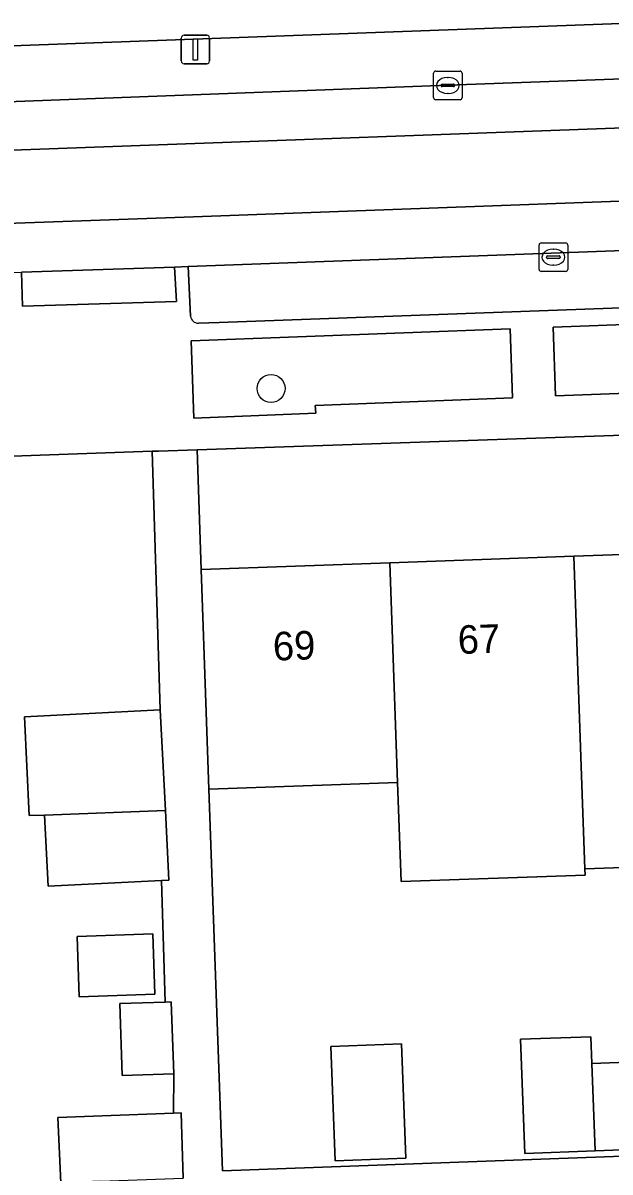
# Model space of a CAD drawing. Extents: x 160554 to 161248, y 385329 to 386506.
# Drawn here: x 160729.21 to 160749.76, y 386114.66 to 386154.93 of the extents above; entities that cross this region are included whole.
import ezdxf

# ---------------------------------------------------------------- set-up
doc = ezdxf.new("R2010")
doc.units = 0
for name, color, linetype in [('IMGEO_Boom', 7, 'Continuous'), ('IMGEO_Erf', 7, 'Continuous'), ('IMGEO_Groenvoorziening', 7, 'Continuous'), ('IMGEO_Kolk', 7, 'Continuous'), ('IMGEO_Lichtmast', 7, 'Continuous'), ('IMGEO_Pand', 7, 'Continuous'), ('IMGEO_Pand_nummerreeks', 7, 'Continuous'), ('IMGEO_Parkeervlak_open', 7, 'Continuous'), ('IMGEO_Rijbaan_lokaal_gesloten', 7, 'Continuous'), ('IMGEO_Rijbaan_lokaal_open', 7, 'Continuous'), ('IMGEO_Voetpad_open', 7, 'Continuous')]:
    doc.layers.add(name, color=color, linetype=linetype)

msp = doc.modelspace()

# ---------------------------------------------------------------- linework, layer by layer
at = {"layer": 'IMGEO_Boom'}
msp.add_circle((160737.894, 386142.121), 0.489, dxfattribs=at)
at = {"layer": 'IMGEO_Erf'}
for points in [[(160809.404, 386142.522), (160806.477, 386142.421), (160735.299, 386139.972), (160735.443, 386135.774), (160742.047, 386136.009), (160748.493, 386136.239), (160754.939, 386136.469), (160761.385, 386136.699), (160767.831, 386136.929), (160774.276, 386137.158), (160780.722, 386137.388), (160787.168, 386137.618), (160793.614, 386137.848), (160800.06, 386138.078), (160806.664, 386138.313), (160806.695, 386137.434), (160809.588, 386137.538)], [(160731.097, 386122.915), (160733.753, 386123.006), (160733.826, 386120.894), (160731.17, 386120.803)], [(160754.083, 386118.653), (160754.197, 386115.59), (160749.237, 386115.405), (160746.777, 386115.313), (160746.629, 386119.313), (160749.094, 386119.404), (160749.127, 386118.469)], [(160742.611, 386115.143), (160740.133, 386115.051), (160739.984, 386119.067), (160742.462, 386119.159)]]:
    msp.add_lwpolyline(points, close=True, dxfattribs=at)
for points in [[(160734.925, 386110.713), (160732.101, 386110.573), (160731.914, 386114.337), (160730.536, 386114.286), (160730.422, 386116.577), (160734.474, 386116.727), (160734.482, 386118.101), (160732.682, 386118.04), (160732.595, 386120.567), (160734.178, 386120.621), (160734.06, 386124.88), (160730.085, 386124.68), (160729.96, 386127.173), (160729.417, 386127.153), (160729.26, 386130.616), (160734.011, 386130.858), (160733.73, 386139.919), (160730.46, 386139.808), (160728.843, 386139.754), (160716.402, 386139.302), (160711.136, 386139.11)], [(160751.879, 386125.398), (160748.884, 386125.291), (160748.892, 386125.068), (160742.446, 386124.838), (160742.322, 386128.314), (160735.717, 386128.079), (160736.193, 386114.703), (160798.286, 386116.987)]]:
    msp.add_lwpolyline(points, dxfattribs=at)
at = {"layer": 'IMGEO_Groenvoorziening'}
msp.add_lwpolyline([(160726.584, 386154.051), (160789.885, 386156.386), (160804.496, 386156.913), (160804.459, 386158.413)], dxfattribs=at)
for points in [[(160764.098, 386144.882), (160747.766, 386144.265), (160747.847, 386141.862), (160764.177, 386142.466)], [(160746.265, 386144.21), (160735.094, 386143.792), (160735.185, 386141.081), (160739.459, 386141.254), (160739.438, 386141.527), (160746.342, 386141.798)]]:
    msp.add_lwpolyline(points, close=True, dxfattribs=at)
at = {"layer": 'IMGEO_Kolk'}
for p, q in [((160743.657, 386153.241), (160744.509, 386153.241)), ((160743.582, 386152.315), (160743.582, 386153.167)), ((160744.07, 386153.021), (160744.095, 386153.021)), ((160744.583, 386153.167), (160744.583, 386152.315)), ((160743.841, 386152.735), (160743.841, 386152.747)), ((160744.279, 386152.698), (160743.881, 386152.698)), ((160743.884, 386152.784), (160744.282, 386152.784)), ((160744.093, 386152.461), (160744.068, 386152.461)), ((160744.325, 386152.747), (160744.325, 386152.735)), ((160744.509, 386152.241), (160743.657, 386152.241)), ((160747.353, 386147.222), (160748.205, 386147.222)), ((160747.278, 386146.296), (160747.278, 386147.148)), ((160747.766, 386147.002), (160747.791, 386147.002)), ((160748.279, 386147.148), (160748.279, 386146.296)), ((160747.537, 386146.716), (160747.537, 386146.728)), ((160747.975, 386146.679), (160747.577, 386146.679)), ((160747.58, 386146.765), (160747.978, 386146.765)), ((160747.789, 386146.442), (160747.764, 386146.442)), ((160748.021, 386146.728), (160748.021, 386146.716)), ((160748.205, 386146.222), (160747.353, 386146.222))]:
    msp.add_line(p, q, dxfattribs=at)
for points in [[(160743.657, 386153.241), (160744.509, 386153.241)], [(160743.582, 386152.315), (160743.582, 386153.167)], [(160744.583, 386153.167), (160744.583, 386152.315)], [(160744.509, 386152.241), (160743.657, 386152.241)], [(160747.353, 386147.222), (160748.205, 386147.222)], [(160747.278, 386146.296), (160747.278, 386147.148)], [(160748.279, 386147.148), (160748.279, 386146.296)], [(160748.205, 386146.222), (160747.353, 386146.222)]]:
    msp.add_lwpolyline(points, dxfattribs=at)
for centre, radius, start, end in [((160743.659, 386153.165), 0.0765, 91.552, 178.448), ((160743.659, 386153.165), 0.0765, 91.552, 178.448), ((160744.507, 386153.165), 0.0765, 1.552, 88.448), ((160744.507, 386153.165), 0.0765, 1.552, 88.448), ((160743.881, 386152.744), 0.0403, 85.8775, 175.7526), ((160743.878, 386152.734), 0.0366, 178.938, 274.7102), ((160744.282, 386152.741), 0.043, 264.8664, 352.4533), ((160744.286, 386152.746), 0.0386, 1.7309, 96.639), ((160743.659, 386152.317), 0.0765, 181.552, 268.448), ((160743.659, 386152.317), 0.0765, 181.552, 268.448), ((160744.507, 386152.317), 0.0765, 271.552, 358.448), ((160744.507, 386152.317), 0.0765, 271.552, 358.448), ((160747.355, 386147.146), 0.0765, 91.552, 178.448), ((160747.355, 386147.146), 0.0765, 91.552, 178.448), ((160748.203, 386147.146), 0.0765, 1.552, 88.448), ((160748.203, 386147.146), 0.0765, 1.552, 88.448), ((160747.577, 386146.725), 0.0403, 85.8775, 175.7526), ((160747.574, 386146.715), 0.0366, 178.938, 274.7102), ((160747.978, 386146.722), 0.043, 264.8664, 352.4533), ((160747.982, 386146.727), 0.0386, 1.7309, 96.639), ((160747.355, 386146.298), 0.0765, 181.552, 268.448), ((160747.355, 386146.298), 0.0765, 181.552, 268.448), ((160748.203, 386146.298), 0.0765, 271.552, 358.448), ((160748.203, 386146.298), 0.0765, 271.552, 358.448)]:
    msp.add_arc(centre, radius, start, end, dxfattribs=at)
for centre, major_axis, ratio, start_param, end_param in [((160744.069, 386152.741), (-0.387, 0.002), 0.722429, 4.712389, 7.853982), ((160744.094, 386152.741), (-0.39, 0.002), 0.717154, 1.570796, 4.712389), ((160747.765, 386146.722), (-0.387, 0.002), 0.722429, 4.712389, 7.853982), ((160747.79, 386146.722), (-0.39, 0.002), 0.717154, 1.570796, 4.712389)]:
    msp.add_ellipse(centre, major_axis=major_axis, ratio=ratio, start_param=start_param, end_param=end_param, dxfattribs=at)
at = {"layer": 'IMGEO_Lichtmast'}
for p, q in [((160734.847, 386154.5), (160735.637, 386154.5)), ((160735.637, 386154.5), (160734.847, 386154.5)), ((160734.747, 386153.6), (160734.747, 386154.4)), ((160734.747, 386154.4), (160734.747, 386153.6)), ((160735.737, 386154.4), (160735.737, 386153.6)), ((160735.737, 386153.6), (160735.737, 386154.4)), ((160735.637, 386153.5), (160734.847, 386153.5)), ((160734.847, 386153.5), (160735.637, 386153.5))]:
    msp.add_line(p, q, dxfattribs=at)
msp.add_lwpolyline([(160735.167, 386154.375), (160735.317, 386154.375), (160735.317, 386153.625), (160735.167, 386153.625), (160735.167, 386154.375)], dxfattribs=at)
for centre, start, end in [((160734.847, 386154.4), 90, 180), ((160734.847, 386154.4), 90, 180), ((160735.637, 386154.4), 0, 90), ((160735.637, 386154.4), 360, 90), ((160734.847, 386153.6), 180, 270), ((160734.847, 386153.6), 180, 270), ((160735.637, 386153.6), 270, 0), ((160735.637, 386153.6), 270, 0)]:
    msp.add_arc(centre, 0.1, start, end, dxfattribs=at)
at = {"layer": 'IMGEO_Pand'}
for points in [[(160755.214, 386128.774), (160754.939, 386136.469), (160748.493, 386136.239), (160748.768, 386128.544), (160748.884, 386125.291), (160751.879, 386125.398), (160751.763, 386128.651)], [(160742.047, 386136.009), (160735.443, 386135.774), (160735.621, 386130.778), (160735.717, 386128.079), (160742.322, 386128.314)], [(160748.493, 386136.239), (160742.047, 386136.009), (160742.322, 386128.314), (160742.446, 386124.838), (160748.892, 386125.068), (160748.884, 386125.291), (160748.768, 386128.544)], [(160734.011, 386130.858), (160729.26, 386130.616), (160729.417, 386127.153), (160729.96, 386127.173), (160734.19, 386127.33)], [(160734.19, 386127.33), (160729.96, 386127.173), (160730.085, 386124.68), (160734.06, 386124.88), (160734.314, 386124.893)], [(160731.17, 386120.803), (160733.826, 386120.894), (160733.753, 386123.006), (160731.097, 386122.915)], [(160734.395, 386120.628), (160734.178, 386120.621), (160732.595, 386120.567), (160732.682, 386118.04), (160734.482, 386118.101)], [(160749.127, 386118.469), (160749.094, 386119.404), (160746.629, 386119.313), (160746.777, 386115.313), (160749.237, 386115.405)], [(160739.984, 386119.067), (160740.133, 386115.051), (160742.611, 386115.143), (160742.462, 386119.159)], [(160749.127, 386118.469), (160749.237, 386115.405), (160754.197, 386115.59), (160754.083, 386118.653)], [(160734.742, 386116.737), (160734.474, 386116.727), (160730.422, 386116.577), (160730.536, 386114.286), (160731.914, 386114.337), (160734.812, 386114.445)]]:
    msp.add_lwpolyline(points, close=True, dxfattribs=at)
at = {"layer": 'IMGEO_Parkeervlak_open'}
for points in [[(160806.476, 386149.019), (160734.993, 386146.392), (160735.066, 386144.651)], [(160735.35, 386144.409), (160736.079, 386144.436), (160804.896, 386146.94), (160805.905, 386147.009)]]:
    msp.add_lwpolyline(points, dxfattribs=at)
msp.add_arc((160735.352, 386144.699), 0.29, 189.5686, 269.5619, dxfattribs=at)
at = {"layer": 'IMGEO_Rijbaan_lokaal_gesloten'}
msp.add_lwpolyline([(160834.064, 386154.328), (160833.979, 386156.036), (160832.121, 386155.974), (160826.115, 386155.745), (160796.064, 386154.65), (160780.09, 386154.054), (160762.105, 386153.4), (160744.095, 386152.749), (160725.861, 386152.062), (160714.387, 386151.668), (160713.317, 386151.63), (160703.238, 386151.261), (160702.292, 386151.238), (160690.182, 386150.794), (160689.63, 386150.777), (160689.851, 386149.047), (160748.65, 386151.198), (160802.504, 386153.169), (160827.576, 386154.097)], close=True, dxfattribs=at)
for points in [[(160806.476, 386149.019), (160806.56, 386149.022), (160816.633, 386149.435), (160818.726, 386149.381), (160832.098, 386149.898), (160834.283, 386150.031), (160834.176, 386151.782), (160735.181, 386148.132), (160703.104, 386146.996)], [(160703.22, 386145.271), (160729.151, 386146.198), (160734.513, 386146.374), (160734.993, 386146.392), (160806.476, 386149.019)]]:
    msp.add_lwpolyline(points, dxfattribs=at)
at = {"layer": 'IMGEO_Rijbaan_lokaal_open'}
for points in [[(160834.176, 386151.782), (160834.064, 386154.328), (160827.576, 386154.097), (160802.504, 386153.169), (160748.65, 386151.198), (160689.851, 386149.047), (160690.275, 386145.788), (160694.256, 386146.327), (160697.634, 386146.691)], [(160703.104, 386146.996), (160735.181, 386148.132), (160834.176, 386151.782)], [(160798.286, 386116.987), (160736.193, 386114.703), (160735.717, 386128.079), (160735.621, 386130.778), (160735.443, 386135.774), (160735.299, 386139.972), (160733.95, 386139.926), (160733.794, 386139.921), (160733.73, 386139.919), (160734.011, 386130.858), (160734.19, 386127.33), (160734.314, 386124.893), (160734.06, 386124.88), (160734.178, 386120.621), (160734.395, 386120.628), (160734.482, 386118.101), (160734.474, 386116.727), (160734.742, 386116.737), (160734.812, 386114.445)]]:
    msp.add_lwpolyline(points, dxfattribs=at)
at = {"layer": 'IMGEO_Voetpad_open'}
for points in [[(160842.227, 386158.315), (160814.477, 386157.284), (160814.421, 386158.783), (160804.459, 386158.413), (160804.496, 386156.913), (160789.885, 386156.386), (160726.584, 386154.051)], [(160684.806, 386150.623), (160687.151, 386150.698), (160689.63, 386150.777), (160690.182, 386150.794), (160702.292, 386151.238), (160703.238, 386151.261), (160703.178, 386152.451), (160713.268, 386152.822), (160713.317, 386151.63), (160714.387, 386151.668), (160714.329, 386152.859), (160725.829, 386153.271), (160725.861, 386152.062), (160744.095, 386152.749), (160762.105, 386153.4), (160780.09, 386154.054), (160796.064, 386154.65), (160826.115, 386155.745)], [(160805.905, 386147.009), (160804.896, 386146.94), (160736.079, 386144.436), (160735.35, 386144.409)], [(160735.066, 386144.651), (160734.993, 386146.392), (160734.513, 386146.374), (160734.584, 386145.17), (160729.188, 386145), (160729.151, 386146.198)], [(160705.637, 386139.495), (160711.136, 386139.11), (160716.402, 386139.302), (160728.843, 386139.754), (160730.46, 386139.808), (160733.73, 386139.919), (160733.794, 386139.921), (160733.95, 386139.926), (160735.299, 386139.972), (160806.477, 386142.421), (160809.404, 386142.522), (160813.563, 386142.706), (160816.862, 386142.826), (160820.805, 386142.97), (160824.702, 386143.111), (160835.543, 386143.506)]]:
    msp.add_lwpolyline(points, dxfattribs=at)
for points in [[(160734.513, 386146.374), (160729.151, 386146.198), (160729.188, 386145), (160734.584, 386145.17)], [(160747.766, 386144.265), (160764.098, 386144.882), (160764.177, 386142.466), (160747.847, 386141.862)], [(160735.094, 386143.792), (160746.265, 386144.21), (160746.342, 386141.798), (160739.438, 386141.527), (160739.459, 386141.254), (160735.185, 386141.081)]]:
    msp.add_lwpolyline(points, close=True, dxfattribs=at)
msp.add_arc((160735.352, 386144.699), 0.29, 189.5686, 269.5619, dxfattribs=at)

# ---------------------------------------------------------------- texts
at = {"layer": 'IMGEO_Pand_nummerreeks'}
for s, rotation, p in [('69', 2.0417, (160737.972, 386132.582)), ('67', 2.0397, (160744.446, 386132.813))]:
    msp.add_text(s, height=1, rotation=rotation, dxfattribs=at).set_placement(p)

doc.saveas('drawing.dxf')
